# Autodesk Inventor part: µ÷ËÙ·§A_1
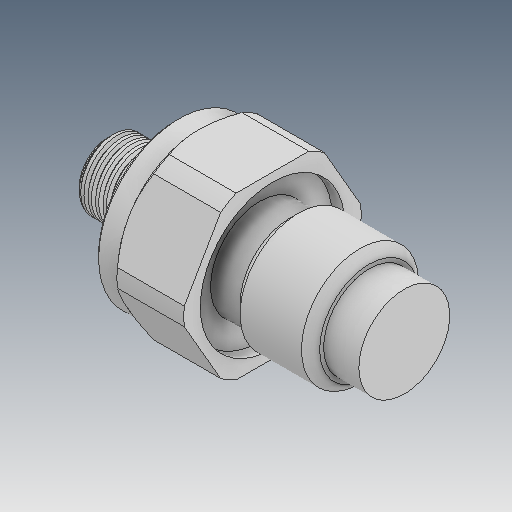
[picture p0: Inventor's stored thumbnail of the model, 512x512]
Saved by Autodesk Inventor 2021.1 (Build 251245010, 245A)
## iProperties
Created: 2019-04
Part Number: µ÷ËÙ·§A_1
Material: Ogólny
Document SubType Name: Modeling
Designer: user
Density: 1 g/cm^3
Appearance: Domyślna
Author: user
Revision Number: ÈÎºÎ
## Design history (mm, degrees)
feature "ÊäÈë1"
node "Bryła1"
